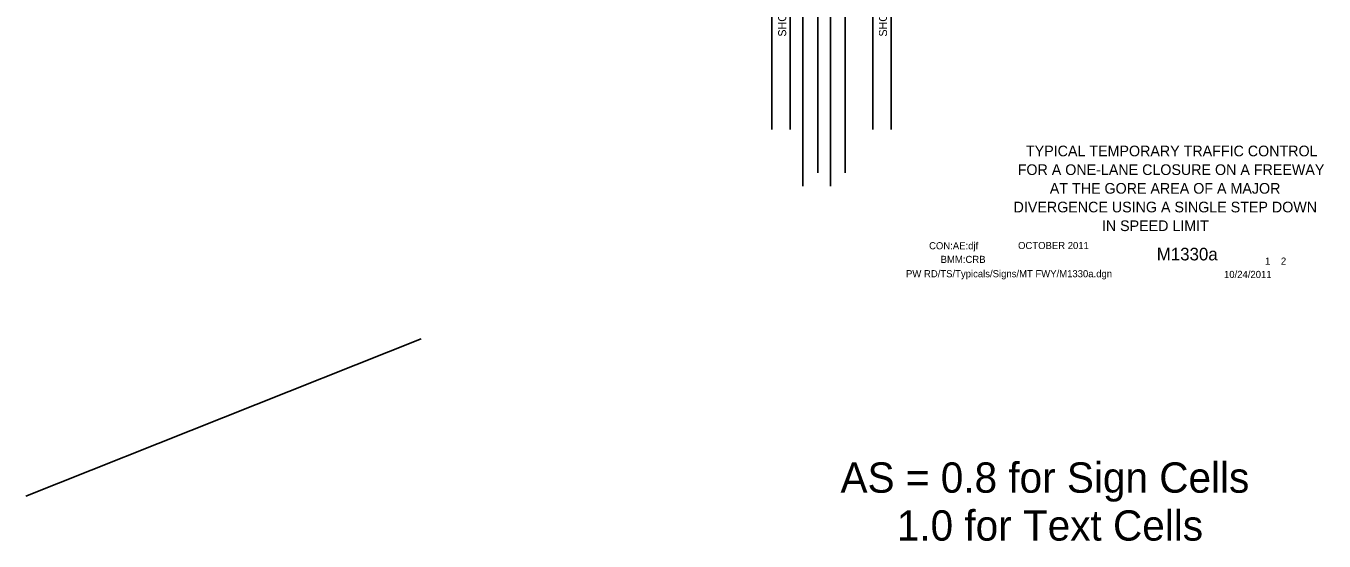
# Model space of a CAD drawing. Extents: x 16303 to 18479, y 5704 to 6974.
# Drawn here: x 16303 to 17435, y 5704 to 6153 of the extents above; entities that cross this region are included whole.
import ezdxf

# ---------------------------------------------------------------- set-up
doc = ezdxf.new("R2010")
doc.units = 0
for name, color, linetype in [('ALI_LEGAL_EX', 7, 'Continuous'), ('BORDER', 7, 'Continuous'), ('BORDER_SIGNAL_WO', 7, 'Continuous'), ('PAVT_EDGE_EX', 7, 'Continuous'), ('TYPICAL_TEXT_DIMEN_PR', 7, 'Continuous')]:
    doc.layers.add(name, color=color, linetype=linetype)

msp = doc.modelspace()

# ---------------------------------------------------------------- linework, layer by layer
at = {"layer": 'ALI_LEGAL_EX'}
for p, q in [((16980.7, 6877), (16980.7, 6013.1)), ((17004.7, 6877), (17004.7, 6013.1)), ((16993.6, 6024.8), (16993.6, 6525.1)), ((17017.6, 6024.8), (17017.6, 6525.1))]:
    msp.add_line(p, q, dxfattribs=at)
for points in [[(16993.6, 6124.8), (16993.6, 6149.8)], [(17017.6, 6124.8), (17017.6, 6149.8)], [(16993.6, 6049.8), (16993.6, 6024.8)]]:
    msp.add_lwpolyline(points, dxfattribs=at)
at = {"layer": 'PAVT_EDGE_EX'}
for p, q in [((16953.6, 6525.1), (16953.6, 6062.7)), ((16969.6, 6525.1), (16969.6, 6062.7)), ((17041.6, 6525.1), (17041.6, 6062.7)), ((17057.6, 6525.1), (17057.6, 6062.7))]:
    msp.add_line(p, q, dxfattribs=at)
at = {"layer": 'TYPICAL_TEXT_DIMEN_PR'}
msp.add_line((16647.8, 5880), (16303.1, 5742.8), dxfattribs=at)

# ---------------------------------------------------------------- texts
at = {"layer": 'BORDER'}
for s, p in [('TYPICAL TEMPORARY TRAFFIC CONTROL', (17175.2, 6039.2)), ('FOR A ONE-LANE CLOSURE ON A FREEWAY', (17168, 6022.9)), ('AT THE GORE AREA OF A MAJOR', (17196, 6006.6)), ('DIVERGENCE USING A SINGLE STEP DOWN ', (17164.4, 5990.3)), ('IN SPEED LIMIT', (17241.4, 5974))]:
    msp.add_text(s, height=9.3, dxfattribs=at).set_placement(p)
at = {"layer": 'BORDER_SIGNAL_WO'}
for s, height, p in [('CON:AE:djf  ', 6.2, (17090.7, 5958.1)), ('    OCTOBER 2011    ', 6.2, (17159.1, 5958.3)), ('    M1330a   ', 11, (17272.9, 5948.4)), ('BMM:CRB   ', 6.2, (17100.8, 5946.2)), (' 1    2 ', 6.2, (17381.4, 5944.7)), ('PW RD/TS/Typicals/Signs/MT FWY/M1330a.dgn      ', 6.2, (17070.6, 5933.7)), ('10/24/2011    ', 6.2, (17347.9, 5933.1)), ('AS = 0.8 for Sign Cells', 26.424, (17013.5, 5745.8)), ('     1.0 for Text Cells', 26.424, (17013.5, 5704))]:
    msp.add_text(s, height=height, dxfattribs=at).set_placement(p)
at = {"layer": 'TYPICAL_TEXT_DIMEN_PR'}
for p in [(16966.1, 6143.6), (17054, 6143.6)]:
    msp.add_text('SHOULDER', height=7, rotation=90, dxfattribs=at).set_placement(p)

doc.saveas('drawing.dxf')
